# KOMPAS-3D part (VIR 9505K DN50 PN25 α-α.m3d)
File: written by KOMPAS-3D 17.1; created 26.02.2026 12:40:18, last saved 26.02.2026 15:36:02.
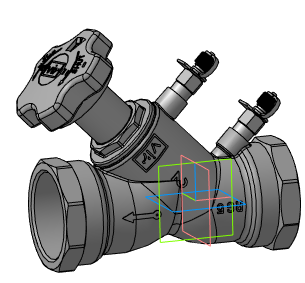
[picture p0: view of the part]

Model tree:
1. Операция без истории:4  (labels: VIR 9505K DN50 PN25 р-р)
